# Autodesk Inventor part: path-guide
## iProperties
Created: 2004-05
Part Number: path-guide
Document SubType Name: Modeling
Designer: CADCIM Technologies
Manufacturer: Standard
Standards Organization: Custom
Author: CADCIM Technologies
